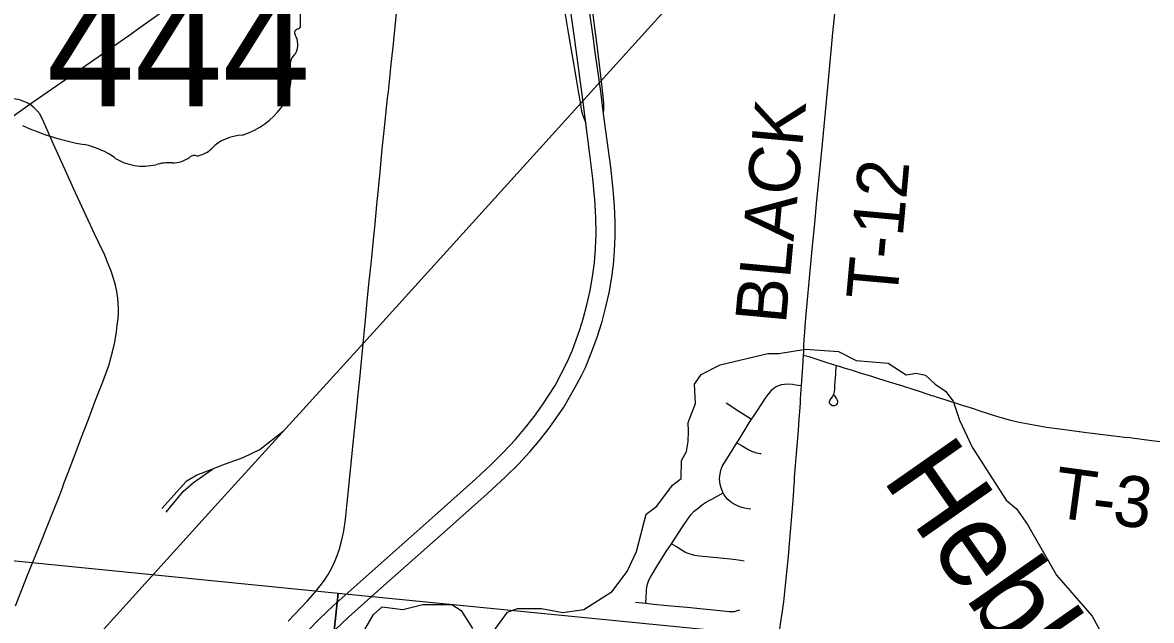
# Model space of a CAD drawing. Extents: x 0 to 34, y 0 to 22.
# Drawn here: x 26.894 to 28.153, y 18.519 to 19.186 of the extents above; entities that cross this region are included whole.
import ezdxf

# ---------------------------------------------------------------- set-up
doc = ezdxf.new("R2010")
doc.units = 0
for name, color, linetype in [('GM_X_City_Street', 7, 'Continuous'), ('GM_X_Interchange_Ramps', 7, 'Continuous'), ('GM_X_Interstate_Route', 7, 'Continuous'), ('GM_X_Minor_River', 7, 'Continuous'), ('GM_X_Minor_River_Text', 7, 'Continuous'), ('GM_X_Rail_Line', 7, 'Continuous'), ('GM_X_Section', 7, 'Continuous'), ('GM_X_State_Location', 7, 'Continuous'), ('GM_X_State_Route', 7, 'Continuous'), ('GM_X_State_Shield', 7, 'Continuous'), ('GM_X_Township_Road', 7, 'Continuous'), ('GM_X_Township_Road_Text', 7, 'Continuous')]:
    doc.layers.add(name, color=color, linetype=linetype)

msp = doc.modelspace()

# ---------------------------------------------------------------- linework, layer by layer
at = {"layer": 'GM_X_City_Street'}
for points in [[(26.8855, 18.5352), (26.8998, 18.571), (26.9117, 18.6003), (26.9226, 18.6274), (26.93, 18.6458), (26.9331, 18.6542), (26.938, 18.6668), (26.9396, 18.6715), (26.9443, 18.6837), (26.9556, 18.7133), (26.9594, 18.7231), (26.9667, 18.7422), (26.9749, 18.7644), (26.9831, 18.7851), (26.9887, 18.8003), (26.99, 18.8041), (26.9914, 18.8086), (26.9939, 18.8183), (26.9963, 18.8293), (26.9982, 18.8409), (26.9992, 18.8483), (27.0002, 18.8558), (27.0006, 18.862), (27.0006, 18.867), (27.0003, 18.872), (26.9998, 18.8782), (26.9987, 18.8857), (26.9971, 18.893), (26.9955, 18.899), (26.9922, 18.9085), (26.9898, 18.9149), (26.9848, 18.9269), (26.9787, 18.9402), (26.9739, 18.95), (26.9645, 18.9703), (26.9504, 19.0006), (26.9425, 19.0181), (26.9351, 19.0345), (26.9277, 19.0508), (26.9171, 19.0747), (26.9127, 19.0838), (26.91, 19.0874), (26.9065, 19.0908), (26.9017, 19.0949)], [(27.7989, 18.7702), (27.8015, 18.7659), (27.8022, 18.7645), (27.8026, 18.7634), (27.8027, 18.7622), (27.8023, 18.7607), (27.8017, 18.7598), (27.801, 18.7591), (27.8001, 18.7586), (27.7992, 18.7583), (27.7982, 18.7582), (27.7972, 18.7583), (27.7962, 18.7586), (27.7949, 18.7596), (27.7943, 18.7606), (27.7939, 18.7617), (27.7939, 18.7629), (27.7941, 18.764), (27.7947, 18.7651), (27.7977, 18.7694), (27.7984, 18.7706), (27.799, 18.7722), (27.7994, 18.774), (27.7997, 18.7768), (27.7998, 18.7795), (27.7999, 18.7814), (27.8002, 18.7854), (27.8004, 18.7893), (27.8007, 18.7936), (27.801, 18.7971), (27.8012, 18.7999), (27.8014, 18.8033)], [(27.706, 18.6431), (27.7029, 18.6434), (27.6989, 18.644), (27.6946, 18.6452), (27.6905, 18.6469), (27.6866, 18.6489), (27.6834, 18.6511), (27.6805, 18.6536), (27.678, 18.6565), (27.6761, 18.6591), (27.6752, 18.661), (27.6746, 18.662), (27.6733, 18.6655), (27.6719, 18.6704), (27.6714, 18.6736), (27.6711, 18.6768), (27.6713, 18.68), (27.672, 18.6842), (27.673, 18.6874), (27.6742, 18.6904), (27.6763, 18.6943), (27.6853, 18.7085), (27.6905, 18.717), (27.6921, 18.7196), (27.7042, 18.7391), (27.7069, 18.7433), (27.7089, 18.7464), (27.7111, 18.7498), (27.7134, 18.7531), (27.7216, 18.7656), (27.7243, 18.7694), (27.7275, 18.7736), (27.7296, 18.776), (27.732, 18.7782), (27.7342, 18.7797), (27.7371, 18.781), (27.7402, 18.782), (27.7434, 18.7825), (27.747, 18.7827), (27.7525, 18.7823), (27.7559, 18.7818), (27.7626, 18.7809)], [(27.6785, 18.7615), (27.6926, 18.7523), (27.7015, 18.7467), (27.7069, 18.7433)], [(27.6905, 18.717), (27.6962, 18.7137), (27.7037, 18.7093), (27.7076, 18.7074), (27.7092, 18.7068), (27.711, 18.7061), (27.7127, 18.7057), (27.7146, 18.7053), (27.7159, 18.7051), (27.7177, 18.7051)], [(27.5889, 18.5381), (27.5891, 18.5443), (27.5895, 18.5517), (27.5901, 18.5567), (27.591, 18.5603), (27.5923, 18.5638), (27.5939, 18.5672), (27.6023, 18.581), (27.6124, 18.5967), (27.6174, 18.6044), (27.6297, 18.6233), (27.636, 18.6326), (27.6394, 18.637), (27.6428, 18.6406), (27.6471, 18.6442), (27.652, 18.648), (27.6567, 18.651), (27.6633, 18.6546), (27.6693, 18.6578), (27.6752, 18.661)], [(27.6174, 18.6044), (27.6229, 18.6011), (27.6282, 18.5979), (27.6325, 18.5954), (27.6345, 18.5943), (27.6369, 18.5933), (27.6394, 18.5926), (27.643, 18.5916), (27.6486, 18.5909), (27.6603, 18.5898), (27.6832, 18.5877), (27.6894, 18.5869), (27.6946, 18.5861), (27.6986, 18.5854)], [(27.5775, 18.5392), (27.5889, 18.5381), (27.5975, 18.5371), (27.6126, 18.5356), (27.6348, 18.5336), (27.6528, 18.5318), (27.6644, 18.5306), (27.6817, 18.5289), (27.6853, 18.5288), (27.6876, 18.5289), (27.6901, 18.5294), (27.6937, 18.5306)]]:
    msp.add_lwpolyline(points, dxfattribs=at)
at = {"layer": 'GM_X_Interchange_Ramps'}
for points in [[(27.4388, 19.4215), (27.4424, 19.4112), (27.4496, 19.3911), (27.4583, 19.3639), (27.4721, 19.3195), (27.4789, 19.2957), (27.4844, 19.2734), (27.4891, 19.2515), (27.4937, 19.2265), (27.5026, 19.1726), (27.5106, 19.1249), (27.5137, 19.107), (27.516, 19.0948), (27.5169, 19.0888), (27.5182, 19.0834), (27.5193, 19.0802), (27.5219, 19.0736)], [(27.5418, 19.0838), (27.5421, 19.0894), (27.5421, 19.0921), (27.5419, 19.0962), (27.5399, 19.1171), (27.5348, 19.1576), (27.5303, 19.1915), (27.5281, 19.2125), (27.5264, 19.2372), (27.5256, 19.2571), (27.5256, 19.2751), (27.5263, 19.2924), (27.5277, 19.3091), (27.5299, 19.3276), (27.5348, 19.3645), (27.5367, 19.383), (27.5375, 19.3985), (27.5376, 19.4074)]]:
    msp.add_lwpolyline(points, dxfattribs=at)
at = {"layer": 'GM_X_Interstate_Route'}
for points in [[(27.5219, 19.0736), (27.5184, 19.1001), (27.5093, 19.1691), (27.5001, 19.235), (27.493, 19.2873), (27.4731, 19.4333), (27.4718, 19.4425), (27.4636, 19.5022), (27.4556, 19.5633)], [(27.5317, 19.1579), (27.5303, 19.1678), (27.5262, 19.1986)], [(27.5101, 18.7791), (27.5171, 18.7922), (27.5214, 18.8011), (27.5287, 18.819), (27.5344, 18.8347), (27.54, 18.8524), (27.5443, 18.8686), (27.5479, 18.8843), (27.5506, 18.8996), (27.5527, 18.9155), (27.554, 18.931), (27.5547, 18.9471), (27.5547, 18.9638), (27.554, 18.9811), (27.5525, 18.9997), (27.5498, 19.0243), (27.5418, 19.0838), (27.5385, 19.1087), (27.5317, 19.1579)], [(27.2119, 18.5071), (27.2249, 18.5205), (27.2401, 18.535), (27.2633, 18.5558), (27.354, 18.6361), (27.3993, 18.6768), (27.4161, 18.6925), (27.4302, 18.7066), (27.4433, 18.7207), (27.4547, 18.7339), (27.4647, 18.7467), (27.4737, 18.7594), (27.4879, 18.7809), (27.5015, 18.8075), (27.507, 18.8203), (27.5153, 18.8435), (27.519, 18.8554), (27.5232, 18.871), (27.5268, 18.8868), (27.5295, 18.9022), (27.5315, 18.9176), (27.5328, 18.9337), (27.5335, 18.9505), (27.5332, 18.9686), (27.532, 18.9885), (27.5298, 19.012), (27.5262, 19.0416), (27.5219, 19.0736)], [(27.1962, 18.4547), (27.1985, 18.458), (27.2075, 18.4699), (27.2175, 18.4819), (27.2292, 18.4948), (27.2423, 18.5082), (27.2572, 18.5223), (27.2927, 18.5543), (27.3639, 18.6174), (27.4117, 18.6599), (27.4322, 18.6789), (27.4468, 18.6933), (27.4595, 18.7068), (27.47, 18.7191), (27.48, 18.7317), (27.489, 18.7443), (27.4972, 18.7567), (27.5101, 18.7791)]]:
    msp.add_lwpolyline(points, dxfattribs=at)
at = {"layer": 'GM_X_Minor_River'}
for points in [[(27.4184, 18.5059), (27.4344, 18.5279), (27.4458, 18.5322), (27.4723, 18.5321), (27.4964, 18.5278), (27.5196, 18.5311), (27.5514, 18.5509), (27.5599, 18.5625), (27.5681, 18.5733), (27.5784, 18.5958), (27.5894, 18.6373), (27.6013, 18.6462), (27.6188, 18.6697), (27.6284, 18.6771), (27.6288, 18.6972), (27.6343, 18.7073), (27.636, 18.7183), (27.6363, 18.7296), (27.6361, 18.7395), (27.6444, 18.7609), (27.6433, 18.7822), (27.6507, 18.793), (27.6718, 18.804), (27.725, 18.8165), (27.7371, 18.8167), (27.7671, 18.8214), (27.8038, 18.8187), (27.8236, 18.8088), (27.8592, 18.8058), (27.8793, 18.7929), (27.8903, 18.7945), (27.9009, 18.7924), (27.9117, 18.7823), (27.9233, 18.7745), (27.9317, 18.7633), (27.9389, 18.7423), (27.9531, 18.7121), (27.9909, 18.6529), (28.0024, 18.6432), (28.0146, 18.6259), (28.0472, 18.5694), (28.0868, 18.5235), (28.1047, 18.4909)], [(27.2656, 18.492), (27.2852, 18.5253), (27.2948, 18.5338), (27.3179, 18.5311), (27.3399, 18.5367), (27.3725, 18.5364), (27.3829, 18.5297), (27.3954, 18.5098)]]:
    msp.add_lwpolyline(points, dxfattribs=at)
at = {"layer": 'GM_X_Rail_Line'}
for points in [[(25.2158, 16.5553), (25.4051, 16.7649), (25.5951, 16.9751), (25.8487, 17.2552), (26.1209, 17.5545), (26.2905, 17.743), (26.4029, 17.8669), (26.4774, 17.9497), (26.594, 18.078), (26.7335, 18.2323), (27.1114, 18.6497), (27.2742, 18.8286), (27.8232, 19.4349), (27.9011, 19.5213)], [(27.1841, 18.7296), (27.1585, 18.7095), (27.1392, 18.7001), (27.1154, 18.6915), (27.1054, 18.6876)], [(27.1054, 18.6876), (27.0878, 18.6808), (27.0759, 18.6738), (27.0488, 18.6438)], [(27.0537, 18.6397), (27.0726, 18.6627), (27.0841, 18.6726), (27.1054, 18.6876)]]:
    msp.add_lwpolyline(points, dxfattribs=at)
at = {"layer": 'GM_X_Section'}
for points in [[(26.2201, 18.6519), (27.2458, 18.5491), (27.1399, 17.5549), (26.1215, 17.6588)], [(27.2458, 18.5491), (28.2231, 18.4529), (28.1329, 17.4467), (27.1399, 17.5549)]]:
    msp.add_lwpolyline(points, close=True, dxfattribs=at)
at = {"layer": 'GM_X_State_Route'}
for points in [[(26.9017, 19.0949), (26.956, 19.1323), (27.0119, 19.1715), (27.0255, 19.181), (27.0433, 19.1936), (27.0636, 19.2078), (27.0786, 19.2181), (27.0929, 19.2278), (27.1074, 19.2374), (27.1208, 19.2461), (27.1323, 19.2532), (27.1442, 19.2607), (27.1575, 19.2688), (27.1748, 19.2787), (27.1992, 19.2923), (27.22, 19.3039)], [(26.7823, 19.0117), (26.8481, 19.0572), (26.8862, 19.0837), (26.9017, 19.0949)]]:
    msp.add_lwpolyline(points, dxfattribs=at)
at = {"layer": 'GM_X_State_Shield'}
for q in [(27.2035, 19.2868), (27.2035, 19.1821)]:
    msp.add_line((27.2035, 19.1821), q, dxfattribs=at)
for centre, major_axis, start_param, end_param in [((27.1996, 19.1817), (0.00393, 0), 5.05454, 6.418171), ((27.2027, 19.1744), (0.00568, 0), 1.883978, 3.671073), ((27.1665, 19.1612), (0.0341, 0), 5.934695, 6.695948), ((27.2167, 19.1383), (0.0248, 0), 2.387724, 3.262537), ((27.1057, 19.125), (0.0874, 0), 5.101752, 6.440018), ((27.0182, 19.2465), (0.2524, 0), 4.195997, 4.488961), ((27.1426, 19.0221), (0.0479, 0), 1.647645, 2.488434), ((26.9429, 18.9884), (0.079, 0), 0.823519, 1.323587), ((27.0819, 19.0589), (0.0282, 0), 4.937069, 5.64225), ((27.0283, 19.0657), (0.0501, 0), 4.026481, 4.996735), ((27.0573, 18.9965), (0.0412, 0), 1.495662, 1.94098), ((27.0609, 19.0507), (0.0267, 0), 4.691044, 5.507374), ((27.0851, 19.0314), (0.00752, 0), 1.147584, 2.315152)]:
    msp.add_ellipse(centre, major_axis=major_axis, ratio=0.8, start_param=start_param, end_param=end_param, dxfattribs=at)
at = {"layer": 'GM_X_Township_Road'}
for points in [[(27.7653, 18.8261), (27.7675, 18.8564), (27.771, 18.8966), (27.7746, 18.9331), (27.7773, 18.9615), (27.7794, 18.9832), (27.7859, 19.0506), (27.7926, 19.1217), (27.7976, 19.1743), (27.8024, 19.2206)], [(27.1898, 18.5178), (27.2115, 18.5408), (27.2197, 18.5501), (27.2256, 18.5573), (27.2303, 18.5638), (27.2343, 18.57), (27.238, 18.5768), (27.2414, 18.5837), (27.2445, 18.5911), (27.2471, 18.5987), (27.2491, 18.6058), (27.2509, 18.6136), (27.2519, 18.6188), (27.2528, 18.624), (27.2534, 18.6285), (27.2543, 18.635), (27.2561, 18.6536), (27.257, 18.6641), (27.2619, 18.7129), (27.2659, 18.7519), (27.2675, 18.768), (27.2698, 18.7883), (27.2714, 18.8038), (27.274, 18.8315), (27.2761, 18.8538), (27.2781, 18.8748), (27.28, 18.894), (27.2827, 18.92), (27.2851, 18.9434), (27.2869, 18.9613), (27.2888, 18.9823), (27.2901, 18.9965), (27.2923, 19.0194), (27.2947, 19.0448), (27.2965, 19.0615), (27.2977, 19.0719), (27.3008, 19.1016), (27.3016, 19.109), (27.3032, 19.1238), (27.3048, 19.1393), (27.3065, 19.1553), (27.3073, 19.1621), (27.3082, 19.1701), (27.3116, 19.2035)], [(26.7926, 19.1106), (26.8083, 19.109), (26.8664, 19.1027), (26.8832, 19.1011), (26.8858, 19.1007), (26.8881, 19.1002), (26.8908, 19.0995), (26.8982, 19.0967), (26.9017, 19.0949)], [(27.7647, 18.8149), (27.765, 18.8172), (27.7652, 18.8223), (27.7653, 18.8251), (27.7653, 18.8261)], [(27.7626, 18.7809), (27.763, 18.7862), (27.7635, 18.7968), (27.7639, 18.8011), (27.7643, 18.8085), (27.7647, 18.8149)], [(27.7647, 18.8149), (27.7706, 18.8131), (27.7786, 18.8105), (27.7842, 18.8088), (27.7896, 18.8071), (27.7968, 18.8048), (27.8014, 18.8033)], [(27.8014, 18.8033), (27.8046, 18.8023), (27.8099, 18.8007), (27.8178, 18.7982), (27.8237, 18.7964)], [(27.8237, 18.7964), (27.8277, 18.7952), (27.8395, 18.7916), (27.8486, 18.7888), (27.8604, 18.785), (27.8677, 18.7827), (27.874, 18.7808), (27.8786, 18.7793), (27.8833, 18.7778), (27.889, 18.776), (27.8951, 18.7741), (27.9002, 18.7723), (27.9023, 18.7716), (27.9047, 18.7709), (27.9077, 18.7699), (27.9099, 18.7692), (27.914, 18.768), (27.9177, 18.7668), (27.9248, 18.7645)], [(27.7495, 18.6086), (27.7514, 18.6312), (27.7527, 18.648), (27.7531, 18.6529), (27.7535, 18.6578), (27.7539, 18.664), (27.7541, 18.6665), (27.7546, 18.6733), (27.7549, 18.6782), (27.7551, 18.6832), (27.7558, 18.6916), (27.7569, 18.7052), (27.7579, 18.7176), (27.759, 18.7314), (27.7598, 18.7431), (27.761, 18.7566), (27.7613, 18.7615), (27.7616, 18.7659), (27.7623, 18.7764), (27.7626, 18.7809)], [(27.9248, 18.7645), (27.928, 18.7635), (27.9349, 18.7613), (27.9429, 18.7587), (27.9495, 18.7566), (27.955, 18.7549), (27.9591, 18.7535), (27.973, 18.749), (27.9789, 18.7471), (27.9837, 18.7457), (27.9957, 18.7424), (28.0054, 18.7401), (28.0219, 18.7369), (28.036, 18.7345), (28.0532, 18.7321), (28.0779, 18.7287), (28.0834, 18.7281), (28.0871, 18.7277), (28.1081, 18.7251), (28.1173, 18.7239), (28.1228, 18.7234), (28.1289, 18.7227), (28.1529, 18.7196), (28.1701, 18.7175)], [(27.7333, 18.4637), (27.7343, 18.4727), (27.7353, 18.4824), (27.7359, 18.489), (27.7369, 18.4983), (27.7377, 18.5049), (27.7382, 18.5092), (27.7394, 18.5173), (27.7412, 18.5292), (27.742, 18.5348), (27.7427, 18.5397), (27.7435, 18.5471), (27.7446, 18.5583), (27.7453, 18.5651), (27.7471, 18.583), (27.7483, 18.5947), (27.7492, 18.6046), (27.7495, 18.6086)]]:
    msp.add_lwpolyline(points, dxfattribs=at)

# ---------------------------------------------------------------- texts
at = {"layer": 'GM_X_Minor_River_Text'}
msp.add_text('Hebble', height=0.0947, rotation=304.9632, dxfattribs=at).set_placement((27.8515, 18.6768))
at = {"layer": 'GM_X_State_Location'}
for s in ['s', 'r']:
    msp.add_text(s, height=0.000189, dxfattribs=at).set_placement((27.035, 19.165))
msp.add_text('444', height=0.000189, rotation=0, dxfattribs=at).set_placement((26.9682, 19.1513))
at = {"layer": 'GM_X_State_Shield'}
msp.add_text('444', height=0.13184, dxfattribs=at).set_placement((26.9205, 19.0924))
at = {"layer": 'GM_X_Township_Road_Text'}
for s, height, rotation, p in [('BLACK', 0.05682, 84.7318, (27.745, 18.8486)), ('T-12', 0.05682, 84.7828, (27.8689, 18.8744)), ('T', 0.0568, 352.2796, (28.0418, 18.6343)), ('3', 0.0568, 353.3061, (28.1082, 18.6257)), ('-', 0.0568, 353.1984, (28.0849, 18.6285))]:
    msp.add_text(s, height=height, rotation=rotation, dxfattribs=at).set_placement(p)

doc.saveas('drawing.dxf')
